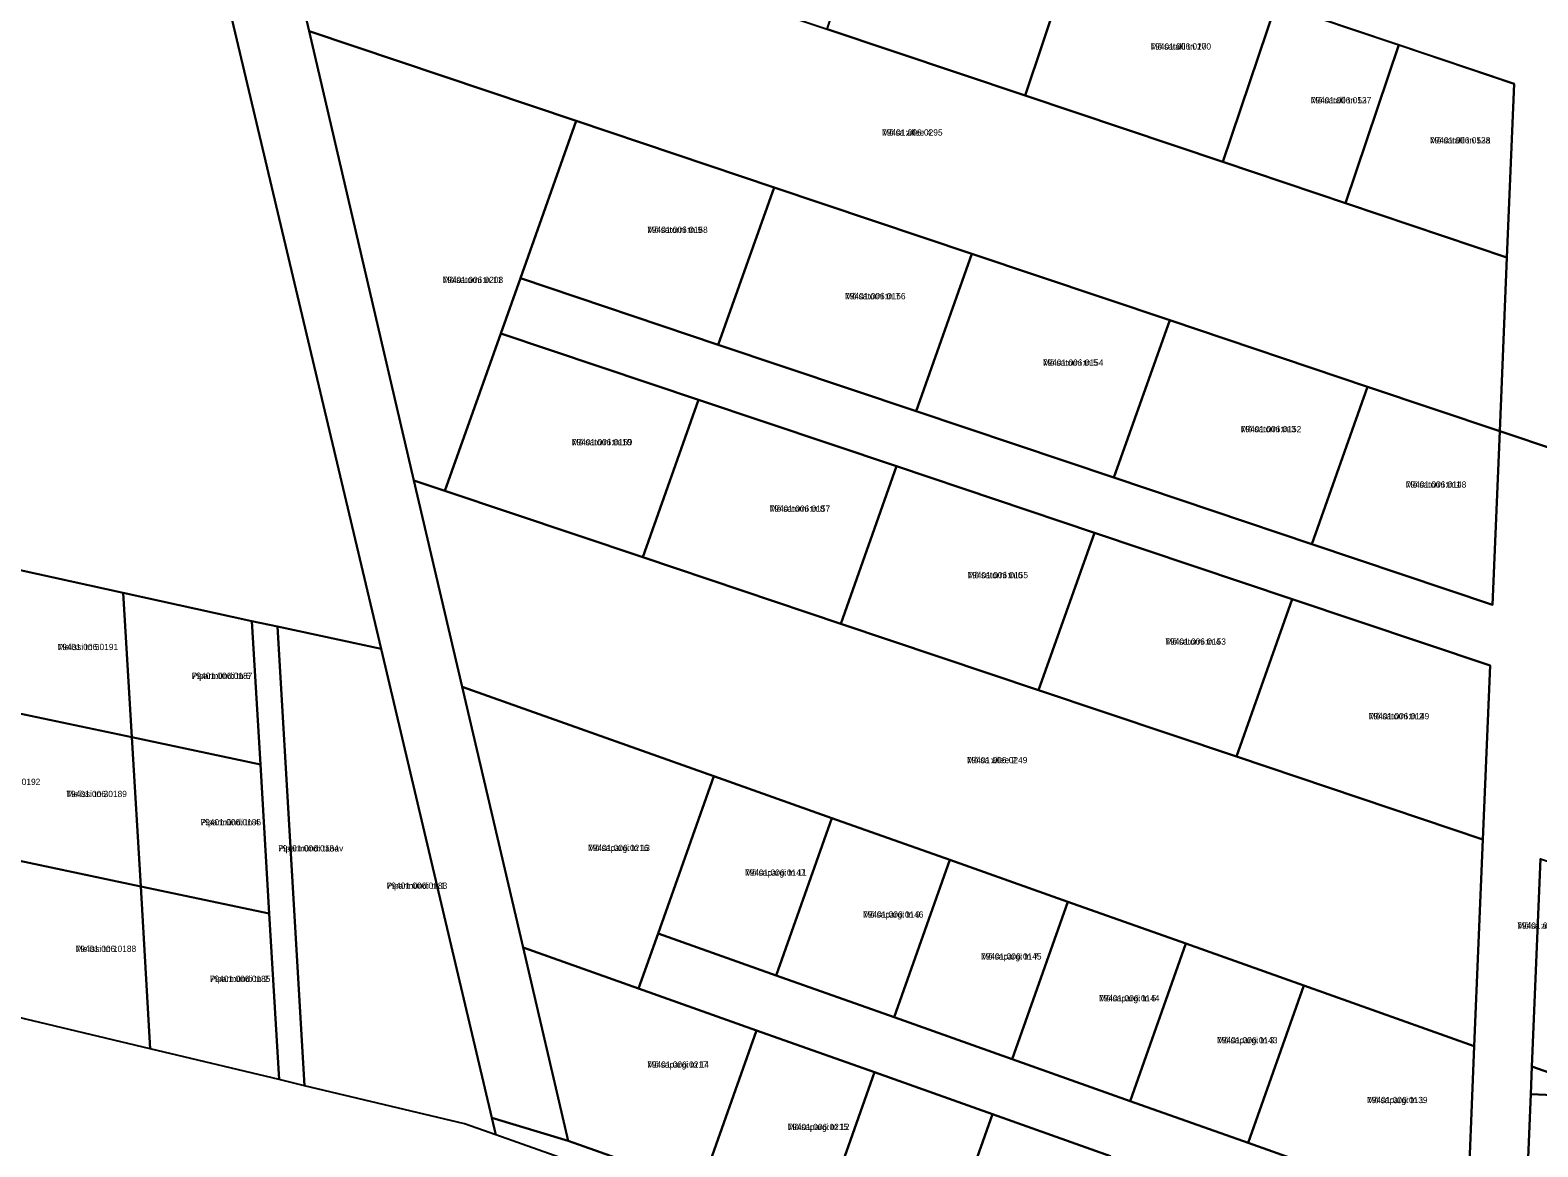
# Model space of a CAD drawing. Extents: x 625111 to 706696, y 6474150 to 6504223.
# Drawn here: x 659027.1 to 659388.4, y 6476713.5 to 6476981 of the extents above; entities that cross this region are included whole.
import ezdxf

# ---------------------------------------------------------------- set-up
doc = ezdxf.new("R2010")
doc.units = 0
for name, color, linetype in [('L_AADRESS', 7, 'Continuous'), ('PIIR', 7, 'Continuous'), ('TUNNUS', 7, 'Continuous')]:
    doc.layers.add(name, color=color, linetype=linetype)

msp = doc.modelspace()

# ---------------------------------------------------------------- linework, layer by layer
at = {"layer": 'PIIR'}
for points in [[(659022.88, 6477285.14), (659027.61, 6477264.87), (659034.62, 6477234.89), (659046.22, 6477185.21), (659054.92, 6477147.94), (659058.14, 6477134.15), (659072.57, 6477072.34), (659083.27, 6477026.56), (659093.96, 6476980.77), (659119.09, 6476873.18), (659130.63, 6476823.75), (659145.22, 6476761.27), (659156.03, 6476714.99), (659137.78, 6476720.47), (659111.23, 6476832.81), (659041.31, 6477128.02), (659034.25, 6477157.62), (659034.75, 6477157.58), (659008.22, 6477269.11)], [(659009.66, 6477150.34), (659041.31, 6477128.02), (659111.23, 6476832.81), (659086.38, 6476838.21), (659080.22, 6476839.48), (659049.44, 6476846.2), (659015.92, 6476853.56)], [(659393.08, 6476880.34), (659379.26, 6476884.98), (659380.98, 6476926.59), (659382.71, 6476968.2), (659325.64, 6476987.37)], [(659285.99, 6476711.31), (659257.72, 6476721.34), (659229.44, 6476731.38), (659201.17, 6476741.41), (659172.9, 6476751.45), (659177.58, 6476764.64), (659205.86, 6476754.61), (659234.13, 6476744.57), (659262.4, 6476734.54), (659290.67, 6476724.5), (659318.94, 6476714.47), (659371.41, 6476695.84), (659373.15, 6476737.67), (659375.2, 6476787.18), (659376.93, 6476828.8), (659329.52, 6476844.71), (659282.12, 6476860.63), (659234.71, 6476876.55), (659187.3, 6476892.47), (659139.9, 6476908.39), (659144.58, 6476921.58), (659191.99, 6476905.66), (659239.39, 6476889.75), (659286.8, 6476873.83), (659334.21, 6476857.91), (659377.53, 6476843.36), (659379.26, 6476884.98), (659393.08, 6476880.34)], [(659389.02, 6476782.54), (659386.96, 6476732.77), (659386.68, 6476726.14), (659382.88, 6476634.47)]]:
    msp.add_lwpolyline(points, dxfattribs=at)
for points in [[(659380.98, 6476926.59), (659379.26, 6476884.98), (659347.59, 6476895.61), (659300.18, 6476911.53), (659252.77, 6476927.45), (659205.37, 6476943.37), (659157.96, 6476959.28), (659093.96, 6476980.77), (659083.27, 6477026.56), (659123.31, 6477013.11), (659170.71, 6476997.19), (659218.11, 6476981.28), (659265.51, 6476965.36), (659312.91, 6476949.45)], [(659278.24, 6477003.28), (659265.51, 6476965.36), (659218.11, 6476981.28), (659230.84, 6477019.2)], [(659325.64, 6476987.37), (659312.91, 6476949.45), (659265.51, 6476965.36), (659278.24, 6477003.28)], [(659355.03, 6476977.5), (659342.3, 6476939.58), (659312.91, 6476949.45), (659325.64, 6476987.37)], [(659157.96, 6476959.28), (659144.58, 6476921.58), (659139.9, 6476908.39), (659126.52, 6476870.69), (659119.09, 6476873.18), (659093.96, 6476980.77)], [(659382.71, 6476968.2), (659380.98, 6476926.59), (659342.3, 6476939.58), (659355.03, 6476977.5)], [(659205.37, 6476943.37), (659191.99, 6476905.66), (659144.58, 6476921.58), (659157.96, 6476959.28)], [(659252.77, 6476927.45), (659239.39, 6476889.75), (659191.99, 6476905.66), (659205.37, 6476943.37)], [(659300.18, 6476911.53), (659286.8, 6476873.83), (659239.39, 6476889.75), (659252.77, 6476927.45)], [(659347.59, 6476895.61), (659334.21, 6476857.91), (659286.8, 6476873.83), (659300.18, 6476911.53)], [(659187.3, 6476892.47), (659173.92, 6476854.77), (659126.52, 6476870.69), (659139.9, 6476908.39)], [(659379.26, 6476884.98), (659377.53, 6476843.36), (659334.21, 6476857.91), (659347.59, 6476895.61)], [(659234.71, 6476876.55), (659221.33, 6476838.85), (659173.92, 6476854.77), (659187.3, 6476892.47)], [(659375.2, 6476787.18), (659373.15, 6476737.67), (659332.32, 6476752.16), (659304.05, 6476762.2), (659275.78, 6476772.23), (659247.51, 6476782.27), (659219.24, 6476792.3), (659190.96, 6476802.34), (659130.63, 6476823.75), (659119.09, 6476873.18), (659126.52, 6476870.69), (659173.92, 6476854.77), (659221.33, 6476838.85), (659268.73, 6476822.93), (659316.14, 6476807.01)], [(659282.12, 6476860.63), (659268.73, 6476822.93), (659221.33, 6476838.85), (659234.71, 6476876.55)], [(659329.52, 6476844.71), (659316.14, 6476807.01), (659268.73, 6476822.93), (659282.12, 6476860.63)], [(659015.92, 6476853.56), (659049.44, 6476846.2), (659051.49, 6476811.64), (659018.01, 6476818.69)], [(659049.44, 6476846.2), (659080.22, 6476839.48), (659082.29, 6476805.14), (659051.49, 6476811.64)], [(659376.93, 6476828.8), (659375.2, 6476787.18), (659316.14, 6476807.01), (659329.52, 6476844.71)], [(659080.22, 6476839.48), (659086.38, 6476838.21), (659092.89, 6476728.16), (659086.77, 6476729.68), (659084.41, 6476769.44), (659082.29, 6476805.14)], [(659086.38, 6476838.21), (659111.23, 6476832.81), (659137.78, 6476720.47), (659138.74, 6476716.39), (659131.21, 6476719.07), (659092.89, 6476728.16)], [(659190.96, 6476802.34), (659177.58, 6476764.64), (659172.9, 6476751.45), (659145.22, 6476761.27), (659130.63, 6476823.75)], [(659018.01, 6476818.69), (659051.49, 6476811.64), (659053.61, 6476775.93), (659020.13, 6476782.99)], [(659051.49, 6476811.64), (659082.29, 6476805.14), (659084.41, 6476769.44), (659053.61, 6476775.93)], [(659190.96, 6476802.34), (659219.24, 6476792.3), (659205.86, 6476754.61), (659177.58, 6476764.64)], [(659219.24, 6476792.3), (659247.51, 6476782.27), (659234.13, 6476744.57), (659205.86, 6476754.61)], [(659020.13, 6476782.99), (659053.61, 6476775.93), (659055.92, 6476737), (659022.39, 6476744.96)], [(659247.51, 6476782.27), (659275.78, 6476772.23), (659262.4, 6476734.54), (659234.13, 6476744.57)], [(659386.96, 6476732.77), (659389.02, 6476782.54), (659480.92, 6476751.68), (659469.42, 6476717.2), (659463.17, 6476705.71), (659395.32, 6476729.8)], [(659053.61, 6476775.93), (659084.41, 6476769.44), (659086.77, 6476729.68), (659055.92, 6476737)], [(659275.78, 6476772.23), (659304.05, 6476762.2), (659290.67, 6476724.5), (659262.4, 6476734.54)], [(659145.22, 6476761.27), (659172.9, 6476751.45), (659201.17, 6476741.41), (659187.79, 6476703.72), (659156.03, 6476714.99)], [(659304.05, 6476762.2), (659332.32, 6476752.16), (659318.94, 6476714.47), (659290.67, 6476724.5)], [(659332.32, 6476752.16), (659373.15, 6476737.67), (659371.41, 6476695.84), (659318.94, 6476714.47)], [(659201.17, 6476741.41), (659229.44, 6476731.38), (659216.07, 6476693.68), (659187.79, 6476703.72)], [(659395.32, 6476729.8), (659393.92, 6476725.84), (659386.68, 6476726.14), (659386.96, 6476732.77)], [(659229.44, 6476731.38), (659257.72, 6476721.34), (659244.34, 6476683.65), (659216.07, 6476693.68)], [(659463.17, 6476705.71), (659418.62, 6476624.4), (659417.48, 6476622.22), (659382.88, 6476634.47), (659386.68, 6476726.14), (659393.92, 6476725.84), (659395.32, 6476729.8)], [(659138.74, 6476716.39), (659137.78, 6476720.47), (659156.03, 6476714.99), (659187.79, 6476703.72), (659216.07, 6476693.68), (659244.34, 6476683.65), (659272.61, 6476673.61), (659300.88, 6476663.58), (659329.15, 6476653.54), (659369.07, 6476639.38), (659382.88, 6476634.47), (659417.48, 6476622.22), (659467.32, 6476601.49), (659483.83, 6476587.06), (659480.14, 6476582.97), (659457.3, 6476603.51), (659274.61, 6476668.23)], [(659257.72, 6476721.34), (659285.99, 6476711.31), (659272.61, 6476673.61), (659244.34, 6476683.65)]]:
    msp.add_lwpolyline(points, close=True, dxfattribs=at)

# ---------------------------------------------------------------- texts
at = {"layer": 'L_AADRESS'}
for s, p in [('Mõisatalli tn 10', (659295.57, 6476976.37)), ('Mõisatalli tn 12', (659333.97, 6476963.48)), ('Mõisa allee 4', (659231.25, 6476955.77)), ('Mõisatalli tn 12a', (659362.5, 6476953.89)), ('Mõisatorni tn 9', (659174.97, 6476932.47)), ('Mõisatorni tn 11', (659125.96, 6476920.45)), ('Mõisatorni tn 7', (659222.38, 6476916.56)), ('Mõisatorni tn 5', (659269.78, 6476900.64)), ('Mõisatorni tn 3', (659317.2, 6476884.72)), ('Mõisatorni tn 10', (659156.91, 6476881.58)), ('Mõisatorni tn 1', (659356.73, 6476871.44)), ('Mõisatorni tn 8', (659204.32, 6476865.66)), ('Mõisatorni tn 6', (659251.72, 6476849.74)), ('Melissi tn 5', (659033.71, 6476832.52)), ('Mõisatorni tn 4', (659299.13, 6476833.82)), ('Piparmündi tn 6', (659065.86, 6476825.61)), ('Mõisatorni tn 2', (659347.85, 6476815.95)), ('Mõisa allee 2', (659251.56, 6476805.43)), ('Melissi tn 3', (659035.81, 6476797.31)), ('Piparmündi tn 4', (659067.95, 6476790.54)), ('Piparmündi tänav', (659086.55, 6476784.28)), ('Mõisapargi tn 13', (659160.8, 6476784.39)), ('Mõisapargi tn 11', (659198.41, 6476778.47)), ('Piparmündi tn 1', (659112.56, 6476775.34)), ('Mõisapargi tn 9', (659226.68, 6476768.44)), ('Mõisa allee L3 // Mõisajärve tänav // Mõisapargi tänav // Mõisatorni tänav', (659383.44, 6476765.78)), ('Melissi tn 1', (659038.03, 6476760.23)), ('Mõisapargi tn 7', (659254.96, 6476758.4)), ('Piparmündi tn 2', (659070.19, 6476753.03)), ('Mõisapargi tn 5', (659283.22, 6476748.37)), ('Mõisapargi tn 3', (659311.5, 6476738.33)), ('Mõisapargi tn 14', (659174.97, 6476732.49)), ('Mõisapargi tn 1', (659347.45, 6476724)), ('Mõisapargi tn 12', (659208.61, 6476717.55))]:
    msp.add_text(s, height=1.5, dxfattribs=at).set_placement(p)
at = {"layer": 'TUNNUS'}
for s, p in [('79401:006:0270', (659295.57, 6476976.37)), ('79401:006:0537', (659333.97, 6476963.48)), ('79401:006:0295', (659231.25, 6476955.77)), ('79401:006:0538', (659362.5, 6476953.89)), ('79401:006:0158', (659174.97, 6476932.47)), ('79401:006:0208', (659125.96, 6476920.45)), ('79401:006:0156', (659222.38, 6476916.56)), ('79401:006:0154', (659269.78, 6476900.64)), ('79401:006:0152', (659317.2, 6476884.72)), ('79401:006:0159', (659156.91, 6476881.58)), ('79401:006:0148', (659356.73, 6476871.44)), ('79401:006:0157', (659204.32, 6476865.66)), ('79401:006:0155', (659251.72, 6476849.74)), ('79401:006:0191', (659033.71, 6476832.52)), ('79401:006:0153', (659299.13, 6476833.82)), ('79401:006:0187', (659065.86, 6476825.61)), ('79401:006:0149', (659347.85, 6476815.95)), ('79401:006:0249', (659251.56, 6476805.43)), ('79401:006:0192', (659015.07, 6476800.22)), ('79401:006:0189', (659035.81, 6476797.31)), ('79401:006:0186', (659067.95, 6476790.54)), ('79401:006:0184', (659086.55, 6476784.28)), ('79401:006:0216', (659160.8, 6476784.39)), ('79401:006:0147', (659198.41, 6476778.47)), ('79401:006:0183', (659112.56, 6476775.34)), ('79401:006:0146', (659226.68, 6476768.44)), ('79401:006:0246', (659383.44, 6476765.78)), ('79401:006:0188', (659038.03, 6476760.23)), ('79401:006:0145', (659254.96, 6476758.4)), ('79401:006:0185', (659070.19, 6476753.03)), ('79401:006:0144', (659283.22, 6476748.37)), ('79401:006:0143', (659311.5, 6476738.33)), ('79401:006:0217', (659174.97, 6476732.49)), ('79401:006:0139', (659347.45, 6476724)), ('79401:006:0215', (659208.61, 6476717.55))]:
    msp.add_text(s, height=1.5, dxfattribs=at).set_placement(p)

doc.saveas('drawing.dxf')
